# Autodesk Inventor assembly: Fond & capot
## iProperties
Author: Flavien MARTY
Shininess: 21.0
PropertySet Name: _Private Model Information
Created: 2001-10
Part Number: Fond & capot
Document SubType Name: Assemblage
Designer: Flavien MARTY
Control State: 0
Master: False
Checked Out: False
PropertySet Name: Design Tracking Control
Density: 0.0
Volumn: 0.0
Area: 0.0
PropertySet Name: Model Information
